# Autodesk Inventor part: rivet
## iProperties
Created: 2011-01
Part Number: rivet
Document SubType Name: Modeling
Designer: eric
Density: 1 g/cm^3
Mass: 0.0227797 g
Surface Area: 0.795998 cm^2
Volume: 0.0227797 cm^3
Author: eric
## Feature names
1. Base1
